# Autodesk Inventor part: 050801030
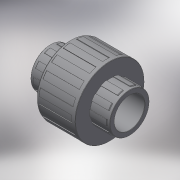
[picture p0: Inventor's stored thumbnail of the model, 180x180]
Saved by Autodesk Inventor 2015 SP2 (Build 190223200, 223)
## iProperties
Created: 2017-10
Part Number: 050801030
Material: Generic
Description: PLASSON THR.UNION+O RING PVC 3"
Document SubType Name: Modeling
Designer: KIM
Density: 1 g/cm^3
Appearance: Default
Author: KIM
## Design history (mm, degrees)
derived "050801.ipt"
feature "Solid1::050801.ipt"
tag "TaggingFeature1"
body "Solid1"
other parameters: "d0" = 125, "d3" = 84.926, "d4" = 84.926, "d5" = 101.9112, "d6" = 98.85386, "d7" = 101.9112, "d8" = 132, "d10" = 33, "d11" = 76.4334, "d14" = 24.75, "d17" = 3.3, "d19" = 129.36, "d20" = 3.3, "d21" = 1.98, "d25" = 13.2, "d26" = 6.6, "d27" = 64.98, "d28" = 0, "d32" = 13.2, "d33" = 6.6, "d35" = 0, "d39" = 0.16, "d45" = 1.52867, "d49" = 360 deg, "d51" = 1.32, "d55" = 360 deg, "d57" = 33, "d58" = 24.75, "d_" = 16, "E_" = 132, "H_" = 125, "l_" = 14, "lt_" = 33, "Z_" = 11, "G_" = 84.926, "d24" = 72.2, "d40" = 1.52867, "d44" = 1.32
